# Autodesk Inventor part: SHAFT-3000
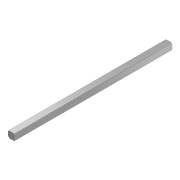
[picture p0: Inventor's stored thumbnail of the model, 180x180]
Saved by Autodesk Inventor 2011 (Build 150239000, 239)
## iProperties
Created: 2007-08
Part Number: SHAFT-3000
Material: Stainless Steel
Document SubType Name: Modeling
Density: 8.08 g/cm^3
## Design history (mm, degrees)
feature "Base1"
workaxis "Work Axis1"
  workplane "Work Plane1"
  workplane "Work Plane2"
body "Solid1"
